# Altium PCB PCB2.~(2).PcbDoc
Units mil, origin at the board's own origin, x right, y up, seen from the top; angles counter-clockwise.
Board outline 1968.5 x 1968.5 mil, 4 copper layers (Top Layer, Internal Plane 1, Internal Plane 2, Bottom Layer), stack 18.2 mil thick; 11 components, 10 nets, 36 pads, 0 vias.
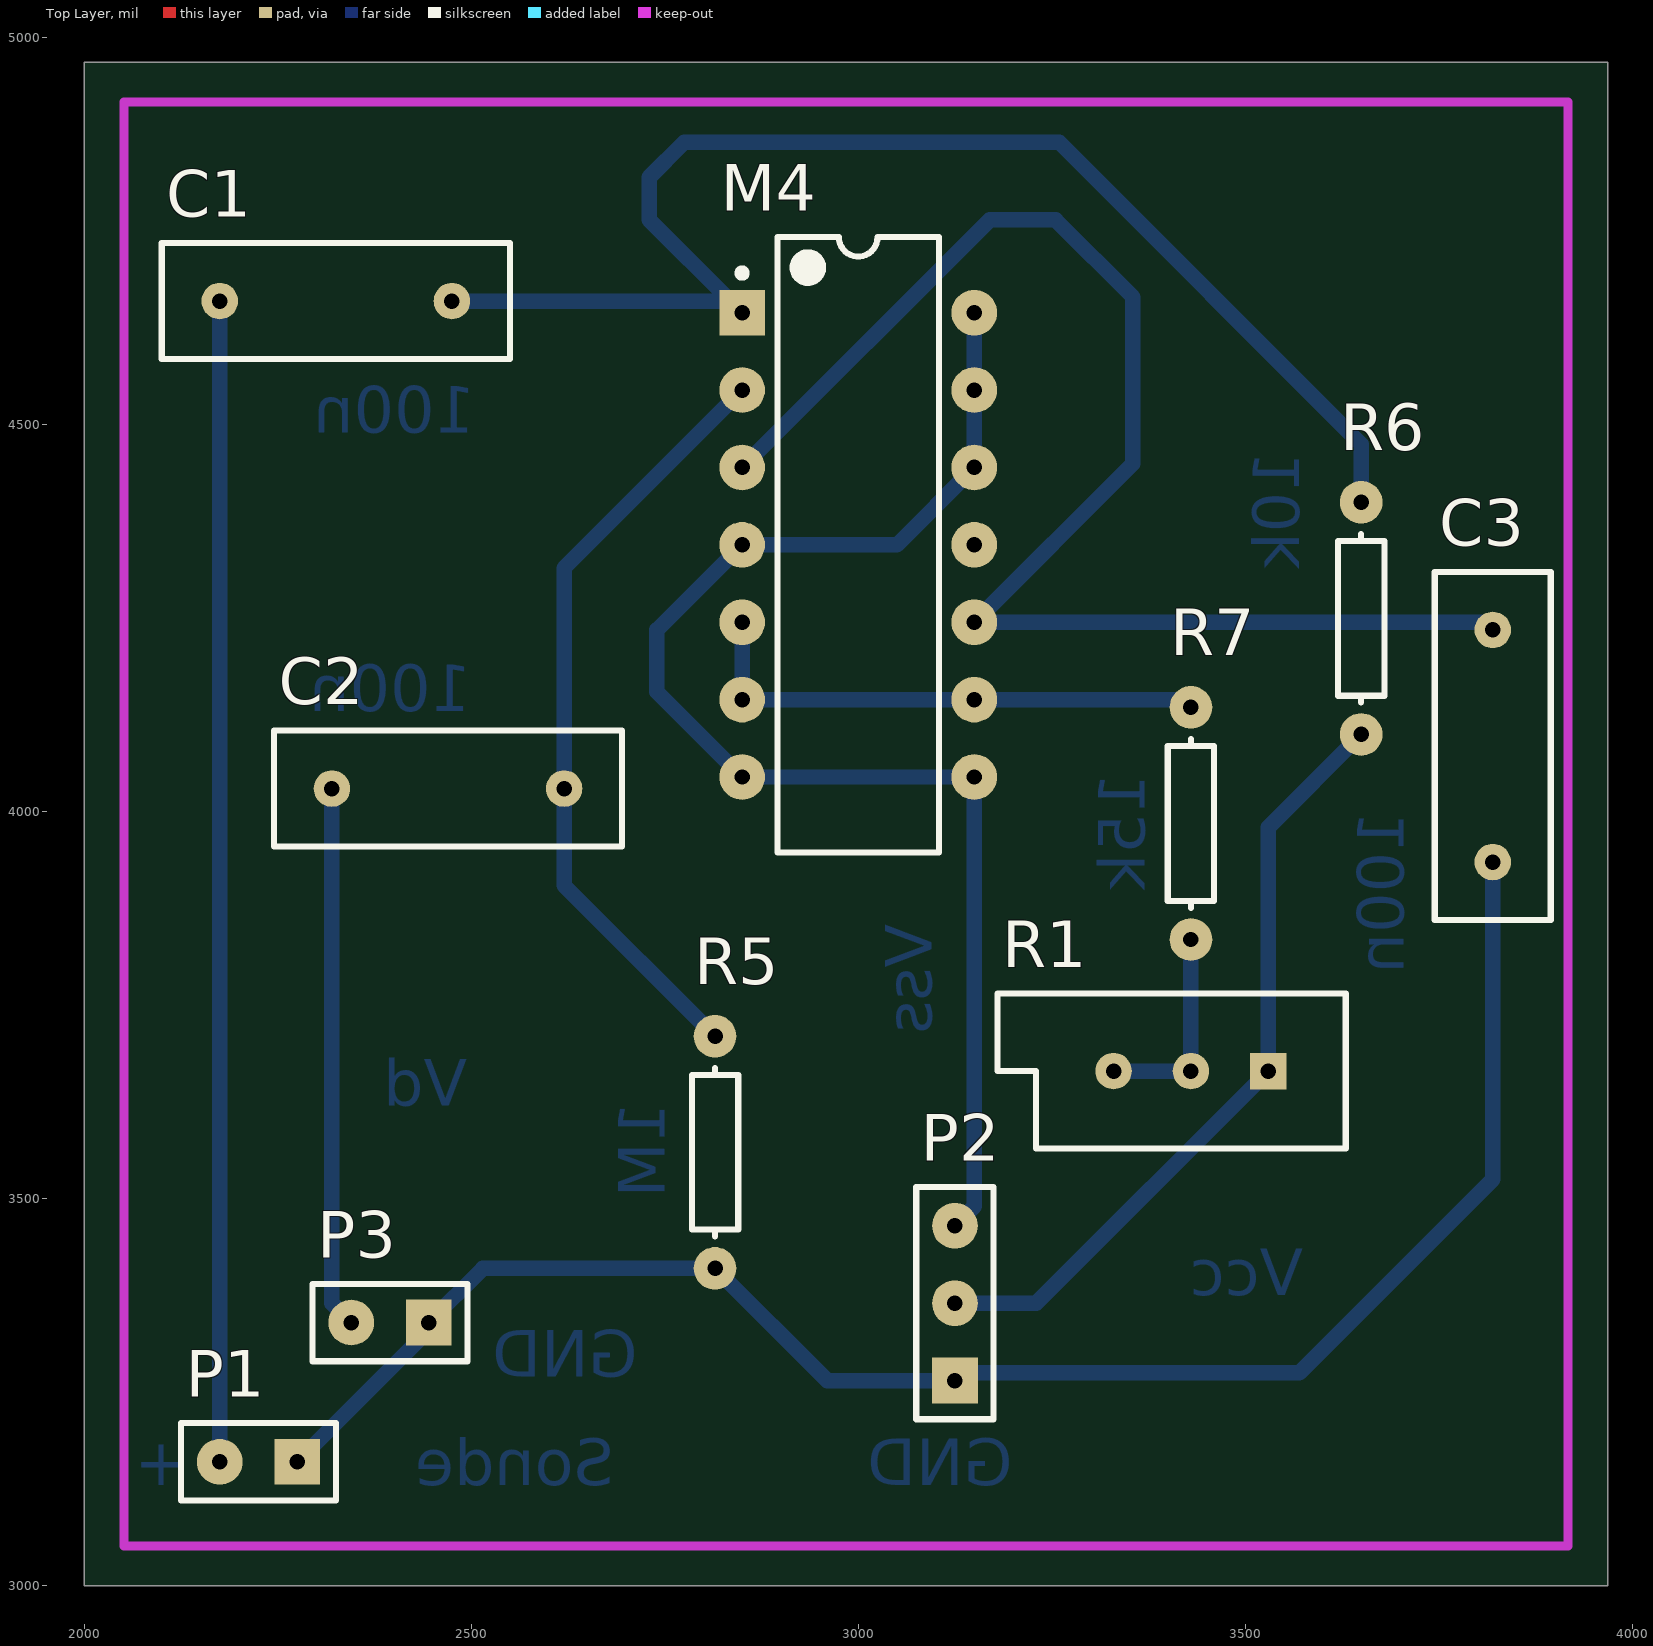
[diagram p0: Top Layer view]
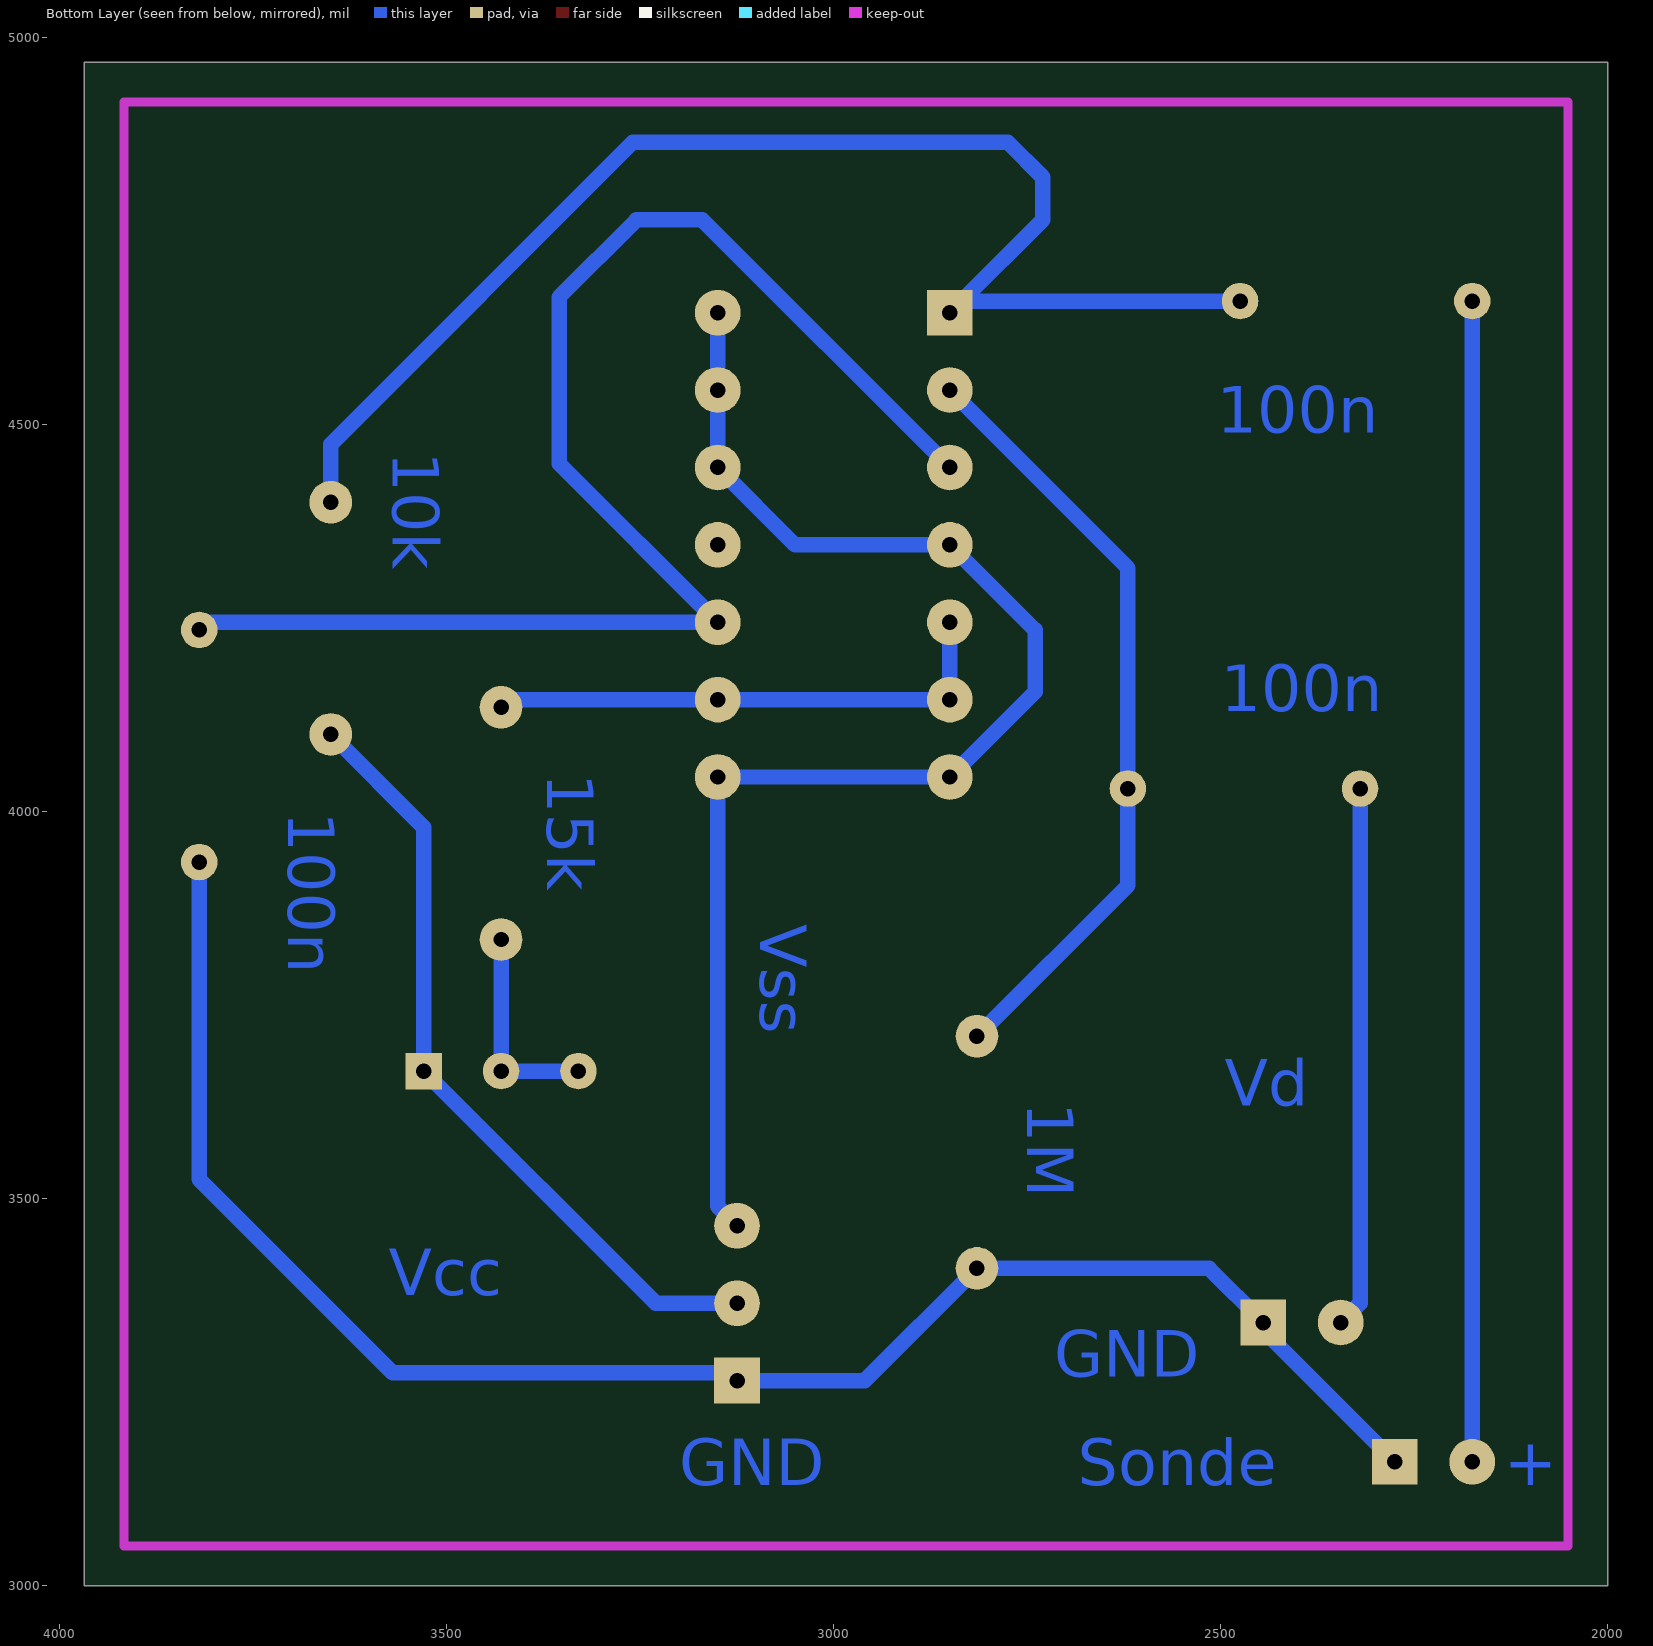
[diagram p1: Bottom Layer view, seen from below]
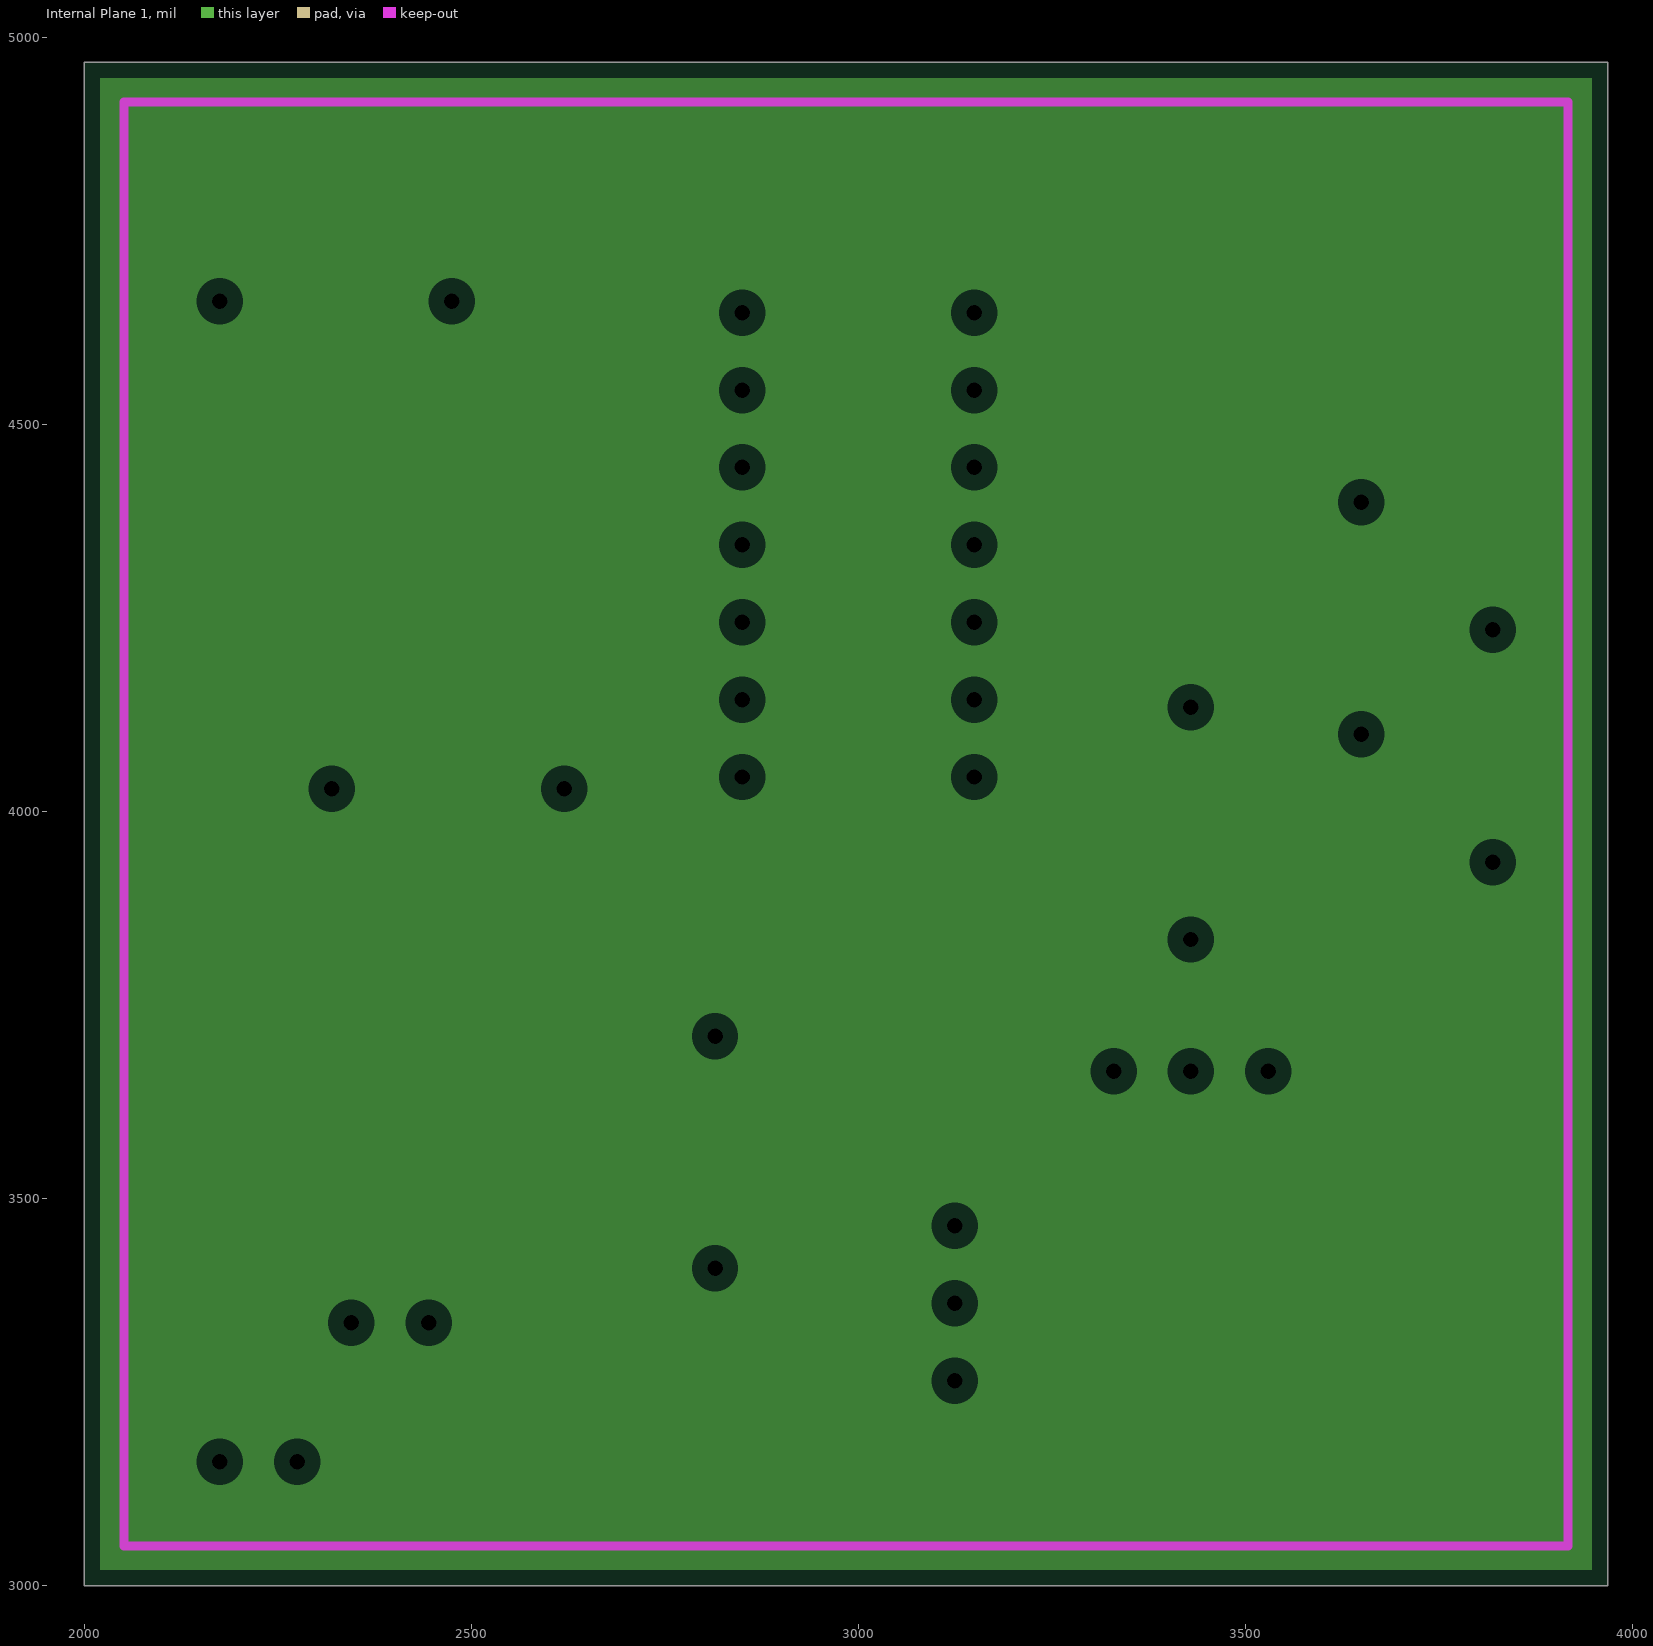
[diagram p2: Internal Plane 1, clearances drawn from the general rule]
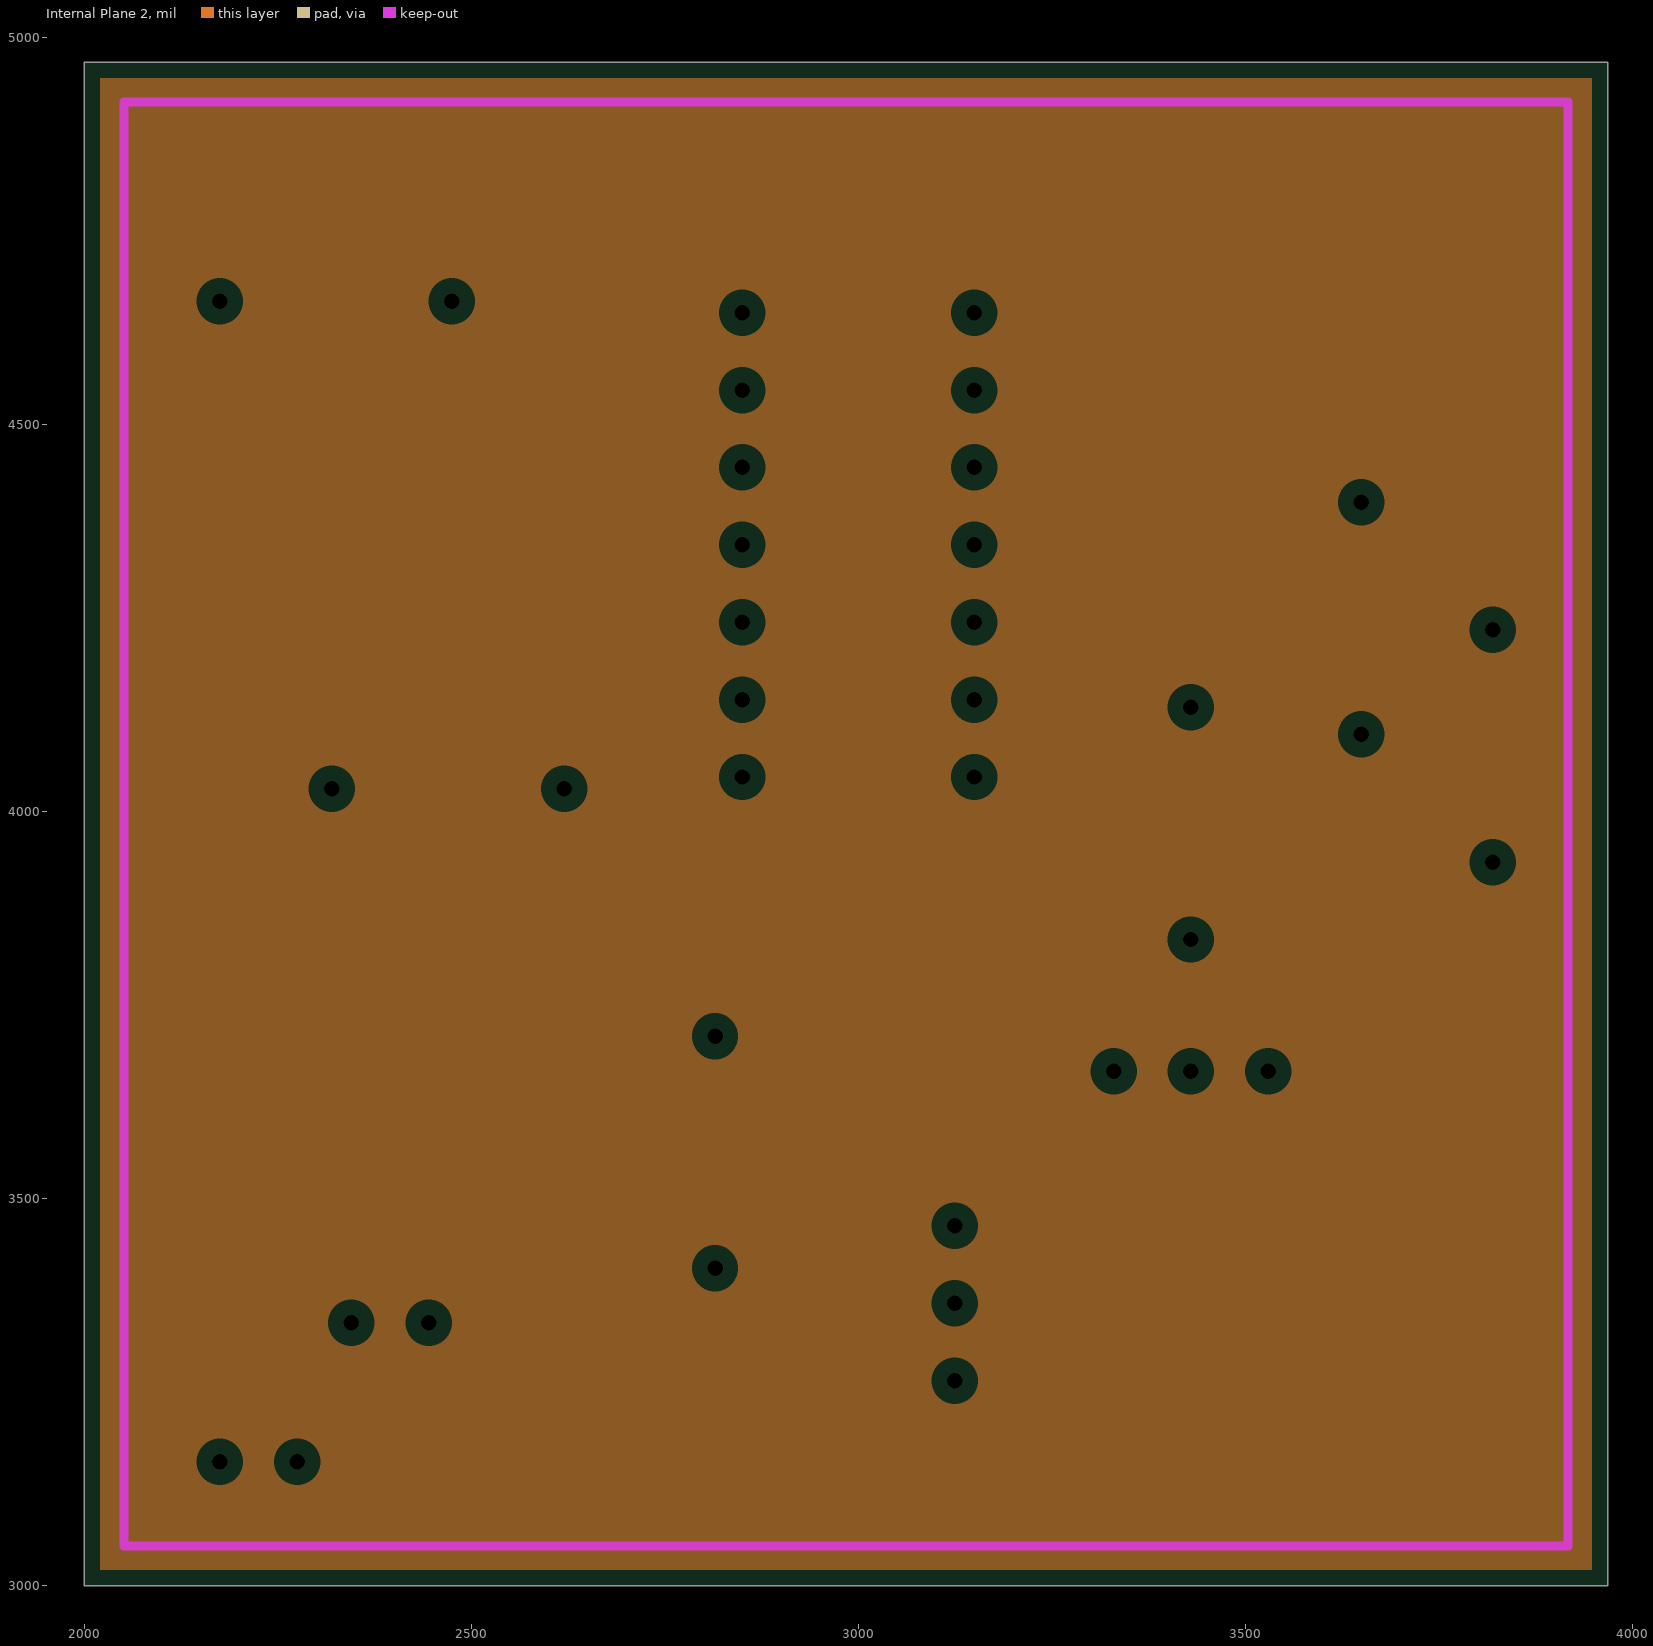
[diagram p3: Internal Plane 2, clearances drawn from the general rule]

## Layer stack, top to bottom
Top Solder: solder mask 0.4, Solder Resist, Dk 3.5
Top Layer: signal copper 1.4
Internal Plane 1: plane copper 1.4
Internal Plane 2: plane copper 1.4
Dielectric 1: dielectric 12.6, FR-4, Dk 4.8
Bottom Layer: signal copper 1.4
Bottom Solder: solder mask 0.4, Solder Resist, Dk 3.5

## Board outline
2000,3000 3968.5,3000 3968.5,4968.5 2000,4968.5

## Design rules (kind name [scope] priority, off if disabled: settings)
Clearance [All] p1: gap=30
PlaneClearance [All] p1: clearance=20
PlaneConnect [All] p1: planeconnectstyle=Relief reliefexpansion=20 reliefentries=4 reliefconductorwidth=10 reliefairgap=10
PolygonConnect [All] p1: connectstyle=Relief reliefconductorwidth=10 reliefentries=4 polygonreliefangle="90 Angle" airgapwidth=10
RoutingVias [All] p1: holewidth=32 width=62 viastyle="Through Hole" minholewidth=28 minwidth=50 maxholewidth=28 maxwidth=50
SolderMaskExpansion [All] p1: expansion=4
Width [All] p1: maxlimit=20 minlimit=20 preferedwidth=20
28 further rules are at their usual default settings.

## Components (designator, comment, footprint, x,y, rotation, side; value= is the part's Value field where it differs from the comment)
C1 "Cap" RAD-0.3 2325,4660 r180 top
C2 "Cap" RAD-0.3 2470,4030 r0 top
C3 "Cap" RAD-0.3 3820,4085 r270 top
M4 "ALD1106" DIP-14 3000,4345 r0 top
P1 "Header 2" HDR1X2 2275,3160 r180 top
P2 "Header 3" HDR1X3 3125,3265 r90 top
P3 "Header 2" HDR1X2 2445,3340 r180 top
R1 "RPot" VR5 3430,3665 r180 top
R5 "Res1" AXIAL-0.3 2815,3560 r90 top
R6 "Res1" AXIAL-0.3 3650,4250 r270 top
R7 "Res1" AXIAL-0.3 3430,3985 r270 top

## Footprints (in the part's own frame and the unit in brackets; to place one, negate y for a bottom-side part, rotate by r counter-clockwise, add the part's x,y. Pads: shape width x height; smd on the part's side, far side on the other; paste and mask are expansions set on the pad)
AXIAL-0.3 [mm] "Axial Device, Thru-Hole; 2 Leads; 0.3 in Pin Spacing"
  round 1.4 hole 0.508: 1(-3.81,0) 2(3.81,0)
  silkscreen extent -2.77,-0.76 2.77,0.76
DIP-14 [mm] "DIP, 14-Pin, Row Spacing 7.62 mm, Pitch 2.54 mm"
  rect 1.5x1.5 hole 0.508: 1(-3.81,7.62)
  round 1.5 hole 0.508: 2(-3.81,5.08) 3(-3.81,2.54) 4(-3.81,0) 5(-3.81,-2.54) 6(-3.81,-5.08) 7(-3.81,-7.62) 8(3.81,-7.62) 9(3.81,-5.08) 10(3.81,-2.54) 11(3.81,0) 12(3.81,2.54) 13(3.81,5.08) 14(3.81,7.62)
  silkscreen extent -3.93,-10.1 2.65,10.1, body extent -3.6,-10.1 3.6,10.1, height 5.08
HDR1X2 [mm] "Connector; Header; 2 Position"
  rect 1.5x1.5 hole 0.508: 1(0,0)
  round 1.5 hole 0.508: 2(2.54,0)
  silkscreen extent -1.27,-1.27 3.81,1.27
HDR1X3 [mm] "Connector; Header; 3 Position"
  rect 1.5x1.5 hole 0.508: 1(0,0)
  round 1.5 hole 0.508: 2(2.54,0) 3(5.08,0)
  silkscreen extent -1.27,-1.27 6.35,1.27
RAD-0.3 [mm] "Radial Cap, Thru-Hole; 2 Leads; 0.3 in Pin Spacing"
  round 1.2 hole 0.508: 1(-3.81,0) 2(3.81,0)
  silkscreen extent -5.71,-1.91 5.71,1.91
VR5 [mm] "Thru-Hole; 3 Leads"
  rect 1.2x1.2 hole 0.508: 1(-2.54,0)
  round 1.2 hole 0.508: 2(0,0) 3(2.54,0)
  silkscreen extent -5.08,-2.54 6.35,2.54

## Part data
C1 C2 C3: "Capacitor"
M4: "Quad N-channel matched MOSFET array"
P1 P3: "Header, 2-Pin"
P2: "Header, 3-Pin"
R1: "Potentiometer"
R5 R6 R7: "Resistor"

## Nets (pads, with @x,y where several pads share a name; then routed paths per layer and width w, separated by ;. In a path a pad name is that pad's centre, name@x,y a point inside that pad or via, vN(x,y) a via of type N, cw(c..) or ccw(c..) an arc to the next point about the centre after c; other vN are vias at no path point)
GND: C3.2 P1.1 P2.1 P3.1 R5.1 | length 2232.2
  Bottom Layer w20: P1.1 2445,3330 P3.1 2515,3410 R5.1 2960,3265 P2.1 3135,3275 3570,3275 3820,3525 C3.2
NetC1_1: C1.1 M4.1 R6.1 | length 1759.9
  Bottom Layer w20: C1.1 M4.1@2835,4660 ; M4.1 M4.1@2835,4660 ; R6.1 3650,4475 3260,4865 2775,4865 2730,4820 2730,4765 M4.1@2835,4660
NetC1_2: C1.2 P1.2 | length 1500
  Bottom Layer w20: P1.2 C1.2
NetC2_1: C2.1 P3.2 | length 700.4
  Bottom Layer w20: C2.1 2320,3365 P3.2
NetC2_2: C2.2 M4.2 R5.2 | length 1011
  Bottom Layer w20: R5.2 2620,3905 C2.2 2620,4315 M4.2
NetC3_1: C3.1 M4.3 M4.10 | length 1858
  Bottom Layer w20: M4.3 3170,4765 3255,4765 3355,4665 3355,4450 M4.10 3810,4245 C3.1
NetM4_4: M4.4 M4.7 M4.8 M4.12 M4.13 M4.14 P2.3 | length 1822.9
  Bottom Layer w20: P2.3 3150,3490 M4.8 M4.7 2740,4155 2740,4235 M4.4 3050,4345 M4.12 M4.13 M4.14
NetM4_5: M4.5 M4.6 M4.9 R7.1 | length 684.1
  Bottom Layer w20: M4.5 M4.6 M4.9 3420,4145 R7.1
NetR1_2: R1.2 R1.3 R7.2 | length 270
  Bottom Layer w20: R1.3 R1.2 R7.2
VCC: P2.2 R1.1 R6.2 | length 1014
  Bottom Layer w20: P2.2 3230,3365 R1.1 3530,3980 R6.2
pads on no net: M4.11

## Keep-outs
Keep-Out Layer:
  lines w11.81: 2051.18,3051.18 2051.18,4917.32 3917.32,4917.32 3917.32,3051.18 2051.18,3051.18

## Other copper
Bottom Layer:
  text "100n" at 2505,4490 h60
  text "10k" at 3570,4465 h60 r90
  text "100n" at 2500,4130 h60
  text "15k" at 3370,4050 h60 r90
  text "100n" at 3705,4000 h60 r90
  text "Vss" at 3095,3855 h60 r90
  text "1M" at 2750,3625 h60 r90
  text "Vd" at 2495,3620 h60
  text "Vcc" at 3575,3375 h60
  text "GND" at 2715,3270 h60
  text "+" at 2065,3130 h60
  text "Sonde" at 2685,3130 h60
  text "GND" at 3200,3130 h60

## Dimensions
2051.18,3051.18 to 2051.18,4917.32 on Mechanical 1
2051.18,3051.18 to 3917.32,3051.18 on Mechanical 1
